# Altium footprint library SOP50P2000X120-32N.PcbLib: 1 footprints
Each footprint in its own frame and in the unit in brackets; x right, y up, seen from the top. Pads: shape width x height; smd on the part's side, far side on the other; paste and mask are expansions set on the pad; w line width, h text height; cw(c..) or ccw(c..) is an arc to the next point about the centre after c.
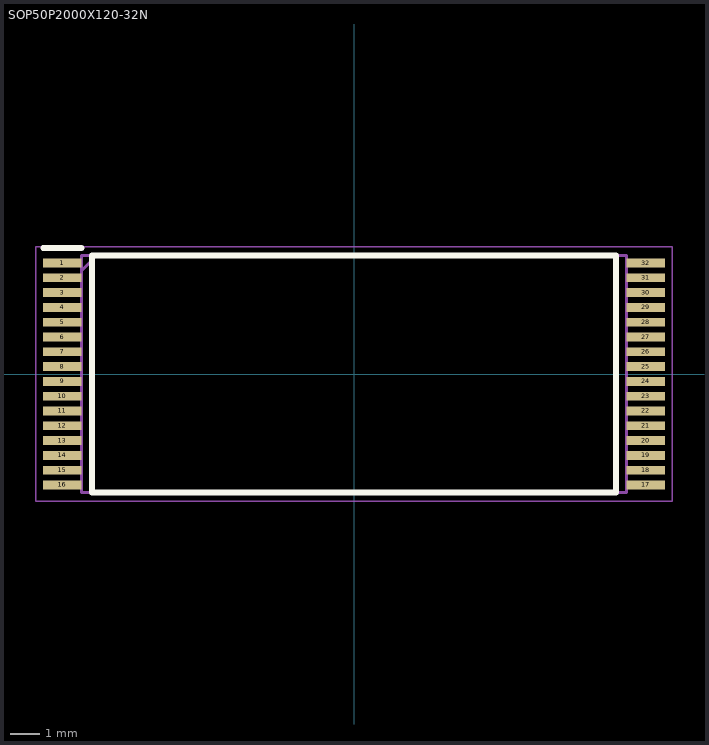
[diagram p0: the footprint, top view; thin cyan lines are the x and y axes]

## SOP50P2000X120-32N [mm]
pads (32):
  rect 1.3x0.3 smd: 1(-9.85,3.75) 2(-9.85,3.25) 3(-9.85,2.75) 4(-9.85,2.25) 5(-9.85,1.75) 6(-9.85,1.25) 7(-9.85,0.75) 8(-9.85,0.25) 9(-9.85,-0.25) 10(-9.85,-0.75) 11(-9.85,-1.25) 12(-9.85,-1.75) 13(-9.85,-2.25) 14(-9.85,-2.75) 15(-9.85,-3.25) 16(-9.85,-3.75) 17(9.85,-3.75) 18(9.85,-3.25) 19(9.85,-2.75) 20(9.85,-2.25) 21(9.85,-1.75) 22(9.85,-1.25) 23(9.85,-0.75) 24(9.85,-0.25) 25(9.85,0.25) 26(9.85,0.75) 27(9.85,1.25) 28(9.85,1.75) 29(9.85,2.25) 30(9.85,2.75) 31(9.85,3.25) 32(9.85,3.75)
Top Overlay:
  lines w0.2: -10.5,4.25 -9.2,4.25 ; -8.85,-4 8.85,-4 8.85,4 -8.85,4 -8.85,-4
Mechanical 15:
  lines w0.1: -9.2,3.5 -8.7,4 ; -9.2,-4 9.2,-4 9.2,4 -9.2,4 -9.2,-4
Mechanical 20:
  lines w0.05: -10.75,-4.3 10.75,-4.3 10.75,4.3 -10.75,4.3 -10.75,-4.3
